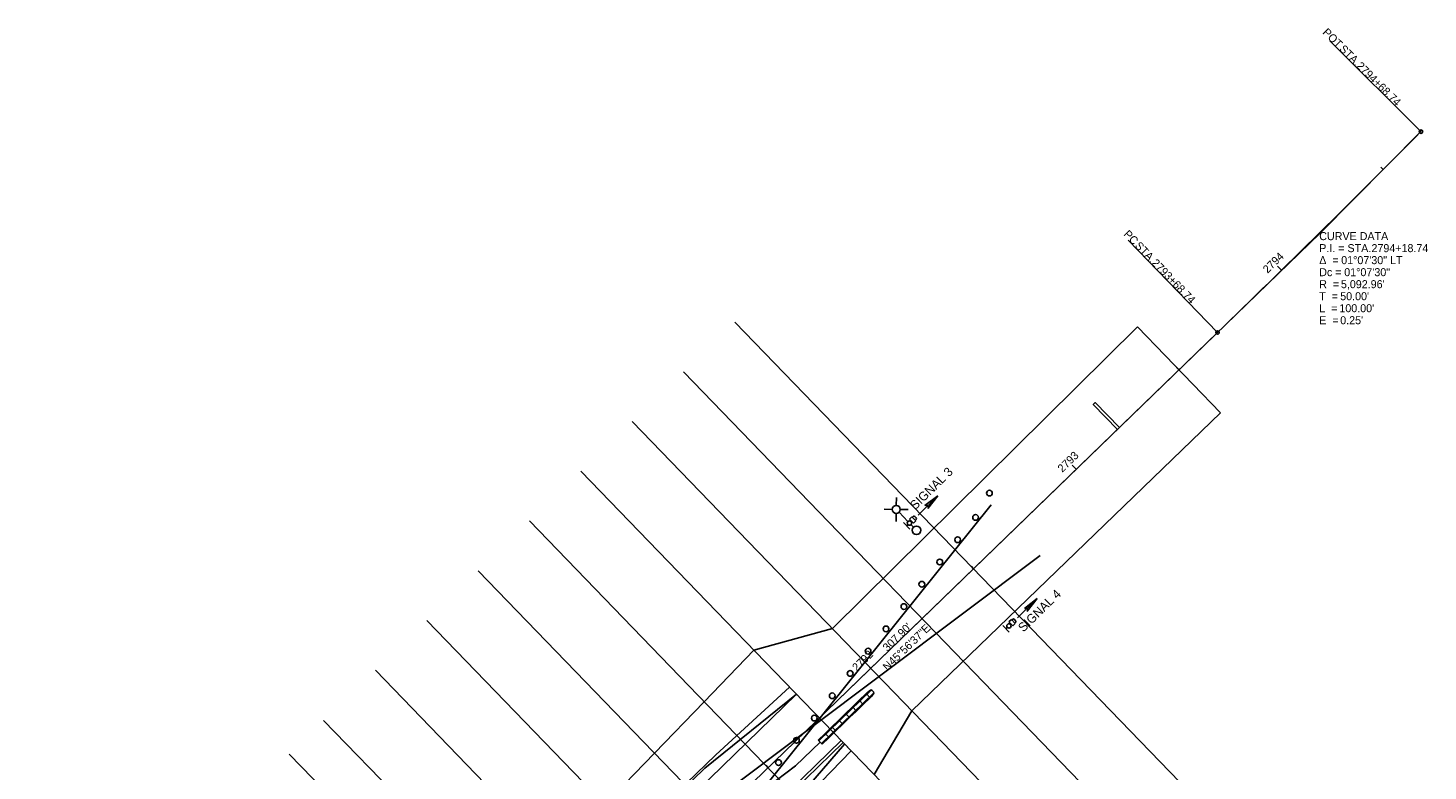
# Model space of a CAD drawing. Extents: x 2376379 to 2383101, y 559608 to 561720.
# Drawn here: x 2376995.7 to 2377485.4, y 561460 to 561719.7 of the extents above; entities that cross this region are included whole.
import ezdxf

# ---------------------------------------------------------------- set-up
doc = ezdxf.new("R2010")
doc.units = 0
for name, color, linetype in [('BD_X_Building', 7, 'Continuous'), ('BR_X_SV_Bottom_of_Beam', 7, 'Continuous'), ('BR_X_SV_Deck_Top', 7, 'Continuous'), ('BR_X_SV_Pier', 7, 'Continuous'), ('DR_X_Elev_Flow', 7, 'Continuous'), ('DR_X_Headwall', 7, 'Continuous'), ('DT_X_Contour_Minor', 7, 'Continuous'), ('HY_X_Spring_Cells', 7, 'Continuous'), ('PM_X_CL_Pass_Proh_Rt', 7, 'Continuous'), ('PM_X_Surveyed_Line', 7, 'Continuous'), ('PV_X_COP', 7, 'Continuous'), ('PV_X_EOP', 7, 'Continuous'), ('RD_X_Cells', 7, 'Continuous'), ('RD_X_GR_Lt', 7, 'Continuous'), ('SV_X_Text', 7, 'Continuous')]:
    doc.layers.add(name, color=color, linetype=linetype)

msp = doc.modelspace()

# ---------------------------------------------------------------- linework, layer by layer
at = {"layer": 'BR_X_SV_Bottom_of_Beam'}
for p, q in [((2377332.62, 561553.02), (2377246.68, 561446.25)), ((2377254.33, 561438.35), (2377281.32, 561469.41))]:
    msp.add_line(p, q, dxfattribs=at)
for centre in [(2377331.94, 561557.13), (2377327.11, 561548.64), (2377320.84, 561540.84), (2377314.58, 561533.05), (2377308.31, 561525.26), (2377302.04, 561517.46), (2377295.78, 561509.67), (2377289.51, 561501.88), (2377283.24, 561494.09), (2377276.98, 561486.29), (2377270.71, 561478.5), (2377264.44, 561470.71), (2377258.18, 561462.92)]:
    msp.add_circle(centre, 1, dxfattribs=at)
at = {"layer": 'BR_X_SV_Deck_Top'}
for p, q in [((2377236.22, 561465.7), (2377262.07, 561489.31)), ((2377262.07, 561489.31), (2377264.5, 561486.8)), ((2377264.5, 561486.8), (2377182.46, 561407.42)), ((2377179.33, 561410.65), (2377236.22, 561465.7))]:
    msp.add_line(p, q, dxfattribs=at)
at = {"layer": 'BR_X_SV_Pier'}
for p, q in [((2377299.39, 561552.83), (2377299.44, 561555.64)), ((2377307.02, 561549.42), (2377313.92, 561556.18)), ((2377309.41, 561552.75), (2377313.92, 561556.18)), ((2377313.92, 561556.18), (2377310.39, 561551.74)), ((2377297.97, 561551.46), (2377295.17, 561551.51)), ((2377299.34, 561550.04), (2377299.3, 561547.24)), ((2377303.46, 561547.2), (2377300.34, 561550.43)), ((2377300.77, 561551.41), (2377303.57, 561551.37)), ((2377304.85, 561548.86), (2377304.03, 561548.06)), ((2377305.39, 561546.67), (2377304.03, 561548.06)), ((2377306.21, 561547.47), (2377304.85, 561548.86)), ((2377305.38, 561549.02), (2377305.03, 561548.69)), ((2377305.38, 561549.02), (2377305.03, 561548.69)), ((2377306.39, 561548), (2377306.04, 561547.66)), ((2377306.39, 561548), (2377306.04, 561547.66)), ((2377304.12, 561544.51), (2377301.85, 561546.82)), ((2377302.9, 561545.75), (2377303.37, 561546.21)), ((2377302.9, 561545.75), (2377303.37, 561546.21)), ((2377303.07, 561545.58), (2377303.54, 561546.04)), ((2377303.07, 561545.58), (2377303.54, 561546.04)), ((2377304.44, 561547.26), (2377304.63, 561547.45)), ((2377304.44, 561547.26), (2377304.63, 561547.45)), ((2377305.4, 561545.21), (2377304.52, 561546.12)), ((2377304.61, 561547.09), (2377304.8, 561547.28)), ((2377304.61, 561547.09), (2377304.8, 561547.28)), ((2377306.21, 561547.47), (2377305.39, 561546.67)), ((2377341.79, 561513.49), (2377348.69, 561520.25)), ((2377344.18, 561516.81), (2377348.69, 561520.25)), ((2377348.69, 561520.25), (2377345.16, 561515.81)), ((2377338.89, 561508.58), (2377336.62, 561510.89)), ((2377337.67, 561509.82), (2377338.14, 561510.28)), ((2377337.67, 561509.82), (2377338.14, 561510.28)), ((2377337.84, 561509.65), (2377338.31, 561510.11)), ((2377337.84, 561509.65), (2377338.31, 561510.11)), ((2377339.62, 561512.93), (2377338.8, 561512.12)), ((2377340.16, 561510.74), (2377338.8, 561512.12)), ((2377339.21, 561511.33), (2377339.4, 561511.52)), ((2377339.21, 561511.33), (2377339.4, 561511.52)), ((2377339.38, 561511.16), (2377339.56, 561511.35)), ((2377339.38, 561511.16), (2377339.56, 561511.35)), ((2377340.98, 561511.54), (2377339.62, 561512.93)), ((2377340.14, 561513.09), (2377339.8, 561512.75)), ((2377340.14, 561513.09), (2377339.8, 561512.75)), ((2377340.98, 561511.54), (2377340.16, 561510.74)), ((2377341.15, 561512.06), (2377340.81, 561511.72)), ((2377341.15, 561512.06), (2377340.81, 561511.72))]:
    msp.add_line(p, q, dxfattribs=at)
for centre, radius in [((2377299.37, 561551.44), 1.4), ((2377303.99, 561546.65), 0.757), ((2377306.44, 561544.13), 1.5), ((2377338.76, 561510.72), 0.757)]:
    msp.add_circle(centre, radius, dxfattribs=at)
for centre in [(2377309.9, 561552.24), (2377344.67, 561516.31)]:
    msp.add_arc(centre, 0.702, 314.3947, 134.3947, dxfattribs=at)
for centre in [(2377305.88, 561548.51), (2377305.88, 561548.51), (2377340.65, 561512.58), (2377340.65, 561512.58)]:
    msp.add_ellipse(centre, major_axis=(0.505, -0.514), ratio=0.45371, start_param=0, end_param=3.141593, dxfattribs=at)
at = {"layer": 'DR_X_Headwall'}
for p in [(2377280.84, 561469.91), (2377259.17, 561441.98)]:
    msp.add_line(p, (2377283.62, 561467.04), dxfattribs=at)
at = {"layer": 'DT_X_Contour_Minor'}
for p, q in [((2377383.73, 561615.24), (2377277.04, 561509.79)), ((2377383.73, 561615.24), (2377412.84, 561585.16)), ((2377412.84, 561585.16), (2377304.82, 561481.08)), ((2377249.6, 561502.2), (2377277.04, 561509.79)), ((2377291.66, 561458.74), (2377304.82, 561481.08))]:
    msp.add_line(p, q, dxfattribs=at)
msp.add_lwpolyline([(2377249.6, 561502.2), (2377232.2, 561484.23), (2377197.43, 561448.26), (2377157.26, 561415.43), (2377142.94, 561428.27), (2377125.48, 561435.43), (2377091.18, 561438.87), (2377089.8, 561425.09), (2377128.5, 561421.22), (2377141.3, 561398.11), (2377119.87, 561384.02)], dxfattribs=at)
at = {"layer": 'HY_X_Spring_Cells'}
for p, q in [((2377482.91, 561683.49), (2377450.99, 561715.21)), ((2377411.73, 561613.26), (2377380.44, 561645.59))]:
    msp.add_line(p, q, dxfattribs=at)
for centre in [(2377482.91, 561683.49), (2377411.73, 561613.26)]:
    msp.add_circle(centre, 0.6, dxfattribs=at)
at = {"layer": 'PM_X_CL_Pass_Proh_Rt'}
msp.add_lwpolyline([(2377376.7, 561579.36), (2377377.42, 561580.06), (2377368.97, 561588.79), (2377368.26, 561588.09)], close=True, dxfattribs=at)
at = {"layer": 'PM_X_Surveyed_Line'}
for p, q in [((2377242.95, 561616.93), (2377409.84, 561444.45)), ((2377391.88, 561427.06), (2377224.99, 561599.54)), ((2377207.02, 561582.16), (2377373.91, 561409.68)), ((2377355.94, 561392.3), (2377189.05, 561564.77)), ((2377171.09, 561547.39), (2377337.98, 561374.91)), ((2377320.01, 561357.53), (2377153.12, 561530)), ((2377135.16, 561512.62), (2377302.04, 561340.14)), ((2377284.08, 561322.76), (2377117.19, 561495.24)), ((2377099.07, 561477.69), (2377266.28, 561305.53)), ((2377087, 561465.93), (2377254.71, 561294.25))]:
    msp.add_line(p, q, dxfattribs=at)
at = {"layer": 'PV_X_COP'}
for p, q in [((2377240.08, 561453.08), (2377349.7, 561535.37)), ((2377232.43, 561460.98), (2377264.46, 561486.84)), ((2377272.3, 561470.57), (2377290.62, 561488.3)), ((2377291.54, 561487.34), (2377273.23, 561469.61)), ((2377284.16, 561482.52), (2377286.32, 561484.6)), ((2377286.32, 561484.6), (2377286.56, 561484.6)), ((2377286.56, 561484.84), (2377288.72, 561486.92)), ((2377286.56, 561484.6), (2377286.56, 561484.84)), ((2377286.56, 561484.6), (2377287.71, 561483.4)), ((2377290.11, 561485.48), (2377287.95, 561483.4)), ((2377288.72, 561486.92), (2377288.95, 561486.92)), ((2377288.95, 561486.92), (2377288.96, 561487.15)), ((2377288.95, 561486.92), (2377290.11, 561485.72)), ((2377288.96, 561487.15), (2377289.27, 561487.46)), ((2377289.27, 561487.46), (2377290.52, 561488.32)), ((2377290.11, 561485.48), (2377290.11, 561485.72)), ((2377290.11, 561485.72), (2377290.35, 561485.72)), ((2377290.66, 561486.02), (2377290.35, 561485.72)), ((2377290.66, 561486.02), (2377291.56, 561487.24)), ((2377281.53, 561479.97), (2377279.37, 561477.88)), ((2377281.53, 561479.97), (2377281.76, 561479.96)), ((2377281.76, 561479.96), (2377281.77, 561480.2)), ((2377281.76, 561479.96), (2377282.92, 561478.77)), ((2377283.92, 561482.29), (2377281.77, 561480.2)), ((2377285.32, 561480.85), (2377283.16, 561478.76)), ((2377283.92, 561482.29), (2377284.16, 561482.28)), ((2377284.16, 561482.28), (2377284.16, 561482.52)), ((2377284.16, 561482.28), (2377285.32, 561481.08)), ((2377285.32, 561480.85), (2377285.32, 561481.08)), ((2377285.32, 561481.08), (2377285.55, 561481.08)), ((2377287.71, 561483.17), (2377285.55, 561481.08)), ((2377287.71, 561483.17), (2377287.71, 561483.4)), ((2377287.71, 561483.4), (2377287.95, 561483.4)), ((2377276.74, 561475.33), (2377274.58, 561473.25)), ((2377276.74, 561475.33), (2377276.97, 561475.33)), ((2377276.97, 561475.33), (2377276.98, 561475.56)), ((2377276.97, 561475.33), (2377278.13, 561474.13)), ((2377279.13, 561477.65), (2377276.98, 561475.56)), ((2377278.13, 561473.89), (2377278.13, 561474.13)), ((2377278.13, 561474.13), (2377278.37, 561474.13)), ((2377280.52, 561476.21), (2377278.37, 561474.13)), ((2377279.13, 561477.65), (2377279.37, 561477.65)), ((2377279.37, 561477.65), (2377279.37, 561477.88)), ((2377279.37, 561477.65), (2377280.53, 561476.45)), ((2377280.52, 561476.21), (2377280.53, 561476.45)), ((2377280.53, 561476.45), (2377280.76, 561476.44)), ((2377282.92, 561478.53), (2377280.76, 561476.44)), ((2377282.92, 561478.53), (2377282.92, 561478.77)), ((2377282.92, 561478.77), (2377283.16, 561478.76)), ((2377264.14, 561461.75), (2377272.76, 561470.09)), ((2377274.34, 561473.01), (2377272.07, 561470.81)), ((2377272.07, 561470.81), (2377273.46, 561469.37)), ((2377275.73, 561471.58), (2377273.46, 561469.37)), ((2377274.34, 561473.01), (2377274.58, 561473.01)), ((2377274.58, 561473.01), (2377274.58, 561473.25)), ((2377274.58, 561473.01), (2377275.74, 561471.81)), ((2377275.73, 561471.58), (2377275.74, 561471.81)), ((2377275.74, 561471.81), (2377275.97, 561471.81)), ((2377278.13, 561473.89), (2377275.97, 561471.81)), ((2377179.85, 561410.11), (2377232.43, 561460.98)), ((2377206.54, 561418.54), (2377264.14, 561461.75))]:
    msp.add_line(p, q, dxfattribs=at)
msp.add_arc((2377290.25, 561487.01), 1.34, 9.8808, 78.2322, dxfattribs=at)
at = {"layer": 'PV_X_EOP'}
for p, q in [((2377469.68, 561670.22), (2377468.83, 561671.07)), ((2377434.13, 561635.06), (2377432.73, 561636.49)), ((2377398.26, 561600.22), (2377397.43, 561601.09)), ((2377362.33, 561565.46), (2377360.94, 561566.89)), ((2377326.4, 561530.69), (2377325.56, 561531.55)), ((2377290.46, 561495.92), (2377289.07, 561497.36)), ((2377254.53, 561461.15), (2377253.7, 561462.01))]:
    msp.add_line(p, q, dxfattribs=at)
at = {"layer": 'RD_X_Cells'}
for p, q in [((2377447.66, 561648.02), (2377482.91, 561683.49)), ((2376995.66, 561210.67), (2377447.66, 561648.02)), ((2377190.46, 561399.15), (2377411.73, 561613.26))]:
    msp.add_line(p, q, dxfattribs=at)
msp.add_arc((2373870.25, 565273.34), 5092.96, 314.05646, 315.18146, dxfattribs=at)
msp.add_arc((2373870.25, 565273.34), 5092.96, 314.05646, 315.18146, dxfattribs=at)
at = {"layer": 'SV_X_Text'}
for p, q in [((2377280.15, 561470.63), (2377198.11, 561391.25)), ((2377280.84, 561469.91), (2377198.8, 561390.53)), ((2377280.15, 561470.63), (2377280.84, 561469.91))]:
    msp.add_line(p, q, dxfattribs=at)

# ---------------------------------------------------------------- texts
at = {"layer": 'BD_X_Building'}
msp.add_text("307.90'", height=2.8, rotation=44.0565, dxfattribs=at).set_placement((2377296.26, 561501.59))
at = {"layer": 'BR_X_SV_Pier'}
for s, p in [('SIGNAL 3', (2377306.01, 561551.1)), ('SIGNAL 4', (2377343.84, 561508.36))]:
    msp.add_text(s, height=3.125, rotation=44.3947, dxfattribs=at).set_placement(p)
at = {"layer": 'DR_X_Elev_Flow'}
msp.add_text('N45°56\'37"E', height=2.8, rotation=44.0565, dxfattribs=at).set_placement((2377296.27, 561494.85))
at = {"layer": 'HY_X_Spring_Cells'}
for s, rotation, p in [('POT', 315.1815, (2377448.29, 561717.95)), (' STA. ', 315.1815, (2377453.4, 561712.87)), ('2794+68.74', 315.1815, (2377460.11, 561706.21)), ('PC', 314.0565, (2377378.71, 561647.44)), (' STA. ', 314.0565, (2377381.9, 561644.15)), ('2793+68.74', 314.0565, (2377388.47, 561637.36))]:
    msp.add_text(s, height=2.8, rotation=rotation, dxfattribs=at).set_placement(p)
at = {"layer": 'PV_X_EOP'}
for s, rotation, p in [('2794', 44.4081, (2377429.24, 561633.78)), ('2793', 44.0565, (2377357.44, 561564.2)), ('2792', 44.0565, (2377285.57, 561494.66))]:
    msp.add_text(s, height=2.8, rotation=rotation, dxfattribs=at).set_placement(p)
at = {"layer": 'RD_X_GR_Lt'}
for s, p in [('CURVE DATA', (2377447.32, 561645.57)), ('P.I. = STA. ', (2377447.32, 561641.37)), ('2794+18.74', (2377465.59, 561641.37)), ('Δ  = ', (2377447.32, 561637.17)), ('Dc = ', (2377447.32, 561632.97)), ('01°07\'30" LT', (2377455, 561637.17)), ('01°07\'30"', (2377456.06, 561632.97)), ('R  = ', (2377447.32, 561628.77)), ("5,092.96'", (2377454.9, 561628.77)), ('T  = ', (2377447.32, 561624.57)), ("50.00'", (2377454.66, 561624.57)), ('L  = ', (2377447.32, 561620.37)), ("100.00'", (2377454.36, 561620.37)), ('E  = ', (2377447.32, 561616.17)), ("0.25'", (2377454.66, 561616.17))]:
    msp.add_text(s, height=2.8, dxfattribs=at).set_placement(p)

doc.saveas('drawing.dxf')
